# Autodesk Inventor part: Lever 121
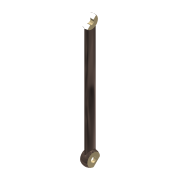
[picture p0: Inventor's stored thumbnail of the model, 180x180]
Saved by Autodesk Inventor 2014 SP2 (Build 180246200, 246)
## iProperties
Created: 2016-02
Part Number: Lever 121
Material: Steel, Cast
Document SubType Name: Modeling
Designer: User
Density: 7.85 g/cm^3
Appearance: Gunmetal - Antique Polished
Author: User
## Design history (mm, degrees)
sketch "Sketch1"
  geometry: L1 (-4, 0)-(4, 0); L2 (-4, 6.928)-(-4, 0); L3 (4, 6.928)-(4, 0); A1 r 8 centre (0, 0) between (4, 6.928) and (-4, 6.928); 2 further points
  constraints: 6 end point, 2 coincident, 2 perpendicular, 2 point on circle, 1 centre point, 1 horizontal, 1 midpoint, 1 parallel
  dimensions: "d0" = 16 diameter of A1; "d1" = 8 distance between parallel lines of L3 L2
revolve "Revolution1" sketch "Sketch1" stored, may be unused: angle "d2" = 90 deg
sketch "Sketch2" dims "d3" = 1.6, "d4" = 6
  geometry: 2 further points; 1 other entity
  constraints: 1 coincident, 2 other
extrude "Extrusion1" join sketch "Sketch2" distance "d5" = 128; taper "d6" = 0 deg
sketch "Sketch3"
  geometry: L1 (-2, 0)-(2, 0); L2 (2, 0)-(2, 6.708); L3 (-2, 6.708)-(-2, 0); A1 r 7 centre (0, 0) between (2, 6.708) and (-2, 6.708); 2 further points; 1 other entity
  constraints: 6 end point, 2 coincident, 2 parallel, 2 point on circle, 1 centre point, 1 horizontal, 1 midpoint, 1 perpendicular, 1 other
  dimensions: "d7" = 7 radius of A1; "d8" = 4 distance between parallel lines of L2 L3
revolve "Revolution2" sketch "Sketch3" stored, may be unused: angle "d9" = 90 deg
hole "Hole1" diameter "d12" = 5; stored, may be unused: countersink angle "d16" = 90 deg, drill point angle "d18" = 118 deg; dims "d10" = 10, "d11" = 10, "d13" = 6, "d14" = 4, "d15" = 2, "d17" = 8
hole "Hole2" diameter "d21" = 6; stored, may be unused: countersink angle "d25" = 90 deg, drill point angle "d27" = 118 deg; dims "d19" = 10, "d20" = 10, "d22" = 6, "d23" = 4, "d24" = 2, "d26" = 8
fillet "Fillet1" dims "d28" = 0.5
body "Solid1"
